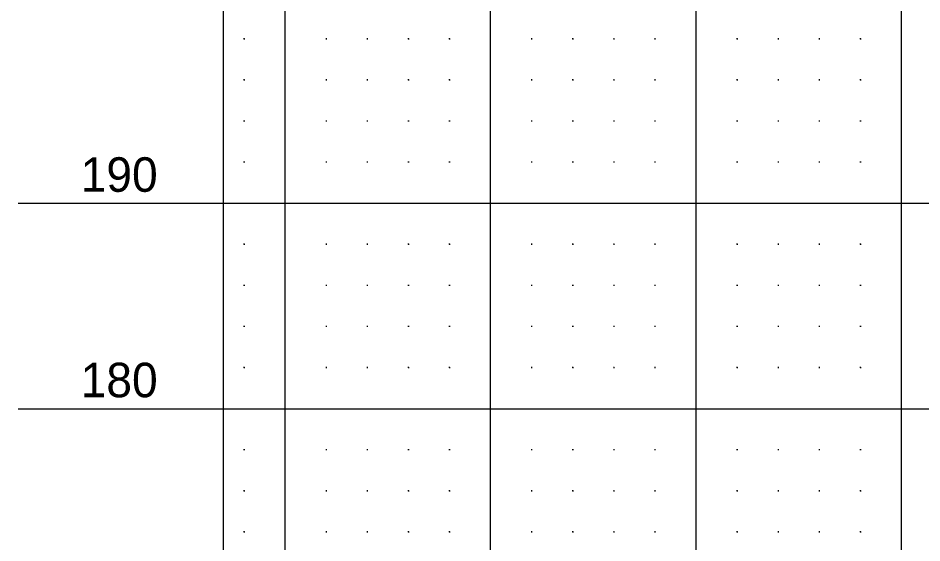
# Model space of a CAD drawing. Extents: x 471 to 2121, y 140 to 650.
# Drawn here: x 471.1 to 691, y 267.3 to 395.1 of the extents above; entities that cross this region are included whole.
import ezdxf

# ---------------------------------------------------------------- set-up
doc = ezdxf.new("R2010")
doc.units = 0
doc.layers.add('DSN_DRFT_Border Grid', color=7, linetype='Continuous')
doc.layers.add('DSN_RDWY_Prof Annotation', color=7, linetype='Continuous')

msp = doc.modelspace()

# ---------------------------------------------------------------- linework, layer by layer
at = {"layer": 'DSN_DRFT_Border Grid'}
for p, q in [((521.06, 150), (521.06, 650)), ((521.06, 150), (521.06, 650)), ((536.06, 150), (536.06, 650)), ((536.06, 150), (536.06, 650)), ((586.06, 150), (586.06, 650)), ((586.06, 150), (586.06, 650)), ((636.06, 150), (636.06, 650)), ((636.06, 150), (636.06, 650)), ((686.06, 150), (686.06, 650)), ((686.06, 150), (686.06, 650)), ((526.18, 390), (525.94, 390)), ((526.18, 390), (525.94, 390)), ((526.06, 390.12), (526.06, 389.88)), ((526.06, 390.12), (526.06, 389.88)), ((546.18, 390), (545.94, 390)), ((546.18, 390), (545.94, 390)), ((546.06, 390.12), (546.06, 389.88)), ((546.06, 390.12), (546.06, 389.88)), ((556.18, 390), (555.94, 390)), ((556.18, 390), (555.94, 390)), ((556.06, 390.12), (556.06, 389.88)), ((556.06, 390.12), (556.06, 389.88)), ((566.18, 390), (565.94, 390)), ((566.18, 390), (565.94, 390)), ((566.06, 390.12), (566.06, 389.88)), ((566.06, 390.12), (566.06, 389.88)), ((576.18, 390), (575.94, 390)), ((576.18, 390), (575.94, 390)), ((576.06, 390.12), (576.06, 389.88)), ((576.06, 390.12), (576.06, 389.88)), ((596.18, 390), (595.94, 390)), ((596.18, 390), (595.94, 390)), ((596.06, 390.12), (596.06, 389.88)), ((596.06, 390.12), (596.06, 389.88)), ((606.18, 390), (605.94, 390)), ((606.18, 390), (605.94, 390)), ((606.06, 390.12), (606.06, 389.88)), ((606.06, 390.12), (606.06, 389.88)), ((616.18, 390), (615.94, 390)), ((616.18, 390), (615.94, 390)), ((616.06, 390.12), (616.06, 389.88)), ((616.06, 390.12), (616.06, 389.88)), ((626.18, 390), (625.94, 390)), ((626.18, 390), (625.94, 390)), ((626.06, 390.12), (626.06, 389.88)), ((626.06, 390.12), (626.06, 389.88)), ((646.18, 390), (645.94, 390)), ((646.18, 390), (645.94, 390)), ((646.06, 390.12), (646.06, 389.88)), ((646.06, 390.12), (646.06, 389.88)), ((656.18, 390), (655.94, 390)), ((656.18, 390), (655.94, 390)), ((656.06, 390.12), (656.06, 389.88)), ((656.06, 390.12), (656.06, 389.88)), ((666.18, 390), (665.94, 390)), ((666.18, 390), (665.94, 390)), ((666.06, 390.12), (666.06, 389.88)), ((666.06, 390.12), (666.06, 389.88)), ((676.18, 390), (675.94, 390)), ((676.18, 390), (675.94, 390)), ((676.06, 390.12), (676.06, 389.88)), ((676.06, 390.12), (676.06, 389.88)), ((526.18, 380), (525.94, 380)), ((526.18, 380), (525.94, 380)), ((526.06, 380.12), (526.06, 379.88)), ((526.06, 380.12), (526.06, 379.88)), ((546.18, 380), (545.94, 380)), ((546.18, 380), (545.94, 380)), ((546.06, 380.12), (546.06, 379.88)), ((546.06, 380.12), (546.06, 379.88)), ((556.18, 380), (555.94, 380)), ((556.18, 380), (555.94, 380)), ((556.06, 380.12), (556.06, 379.88)), ((556.06, 380.12), (556.06, 379.88)), ((566.18, 380), (565.94, 380)), ((566.18, 380), (565.94, 380)), ((566.06, 380.12), (566.06, 379.88)), ((566.06, 380.12), (566.06, 379.88)), ((576.18, 380), (575.94, 380)), ((576.18, 380), (575.94, 380)), ((576.06, 380.12), (576.06, 379.88)), ((576.06, 380.12), (576.06, 379.88)), ((596.18, 380), (595.94, 380)), ((596.18, 380), (595.94, 380)), ((596.06, 380.12), (596.06, 379.88)), ((596.06, 380.12), (596.06, 379.88)), ((606.18, 380), (605.94, 380)), ((606.18, 380), (605.94, 380)), ((606.06, 380.12), (606.06, 379.88)), ((606.06, 380.12), (606.06, 379.88)), ((616.18, 380), (615.94, 380)), ((616.18, 380), (615.94, 380)), ((616.06, 380.12), (616.06, 379.88)), ((616.06, 380.12), (616.06, 379.88)), ((626.18, 380), (625.94, 380)), ((626.18, 380), (625.94, 380)), ((626.06, 380.12), (626.06, 379.88)), ((626.06, 380.12), (626.06, 379.88)), ((646.18, 380), (645.94, 380)), ((646.18, 380), (645.94, 380)), ((646.06, 380.12), (646.06, 379.88)), ((646.06, 380.12), (646.06, 379.88)), ((656.18, 380), (655.94, 380)), ((656.18, 380), (655.94, 380)), ((656.06, 380.12), (656.06, 379.88)), ((656.06, 380.12), (656.06, 379.88)), ((666.18, 380), (665.94, 380)), ((666.18, 380), (665.94, 380)), ((666.06, 380.12), (666.06, 379.88)), ((666.06, 380.12), (666.06, 379.88)), ((676.18, 380), (675.94, 380)), ((676.18, 380), (675.94, 380)), ((676.06, 380.12), (676.06, 379.88)), ((676.06, 380.12), (676.06, 379.88)), ((526.18, 370), (525.94, 370)), ((526.18, 370), (525.94, 370)), ((526.06, 370.12), (526.06, 369.88)), ((526.06, 370.12), (526.06, 369.88)), ((546.18, 370), (545.94, 370)), ((546.18, 370), (545.94, 370)), ((546.06, 370.12), (546.06, 369.88)), ((546.06, 370.12), (546.06, 369.88)), ((556.18, 370), (555.94, 370)), ((556.18, 370), (555.94, 370)), ((556.06, 370.12), (556.06, 369.88)), ((556.06, 370.12), (556.06, 369.88)), ((566.18, 370), (565.94, 370)), ((566.18, 370), (565.94, 370)), ((566.06, 370.12), (566.06, 369.88)), ((566.06, 370.12), (566.06, 369.88)), ((576.18, 370), (575.94, 370)), ((576.18, 370), (575.94, 370)), ((576.06, 370.12), (576.06, 369.88)), ((576.06, 370.12), (576.06, 369.88)), ((596.18, 370), (595.94, 370)), ((596.18, 370), (595.94, 370)), ((596.06, 370.12), (596.06, 369.88)), ((596.06, 370.12), (596.06, 369.88)), ((606.18, 370), (605.94, 370)), ((606.18, 370), (605.94, 370)), ((606.06, 370.12), (606.06, 369.88)), ((606.06, 370.12), (606.06, 369.88)), ((616.18, 370), (615.94, 370)), ((616.18, 370), (615.94, 370)), ((616.06, 370.12), (616.06, 369.88)), ((616.06, 370.12), (616.06, 369.88)), ((626.18, 370), (625.94, 370)), ((626.18, 370), (625.94, 370)), ((626.06, 370.12), (626.06, 369.88)), ((626.06, 370.12), (626.06, 369.88)), ((646.18, 370), (645.94, 370)), ((646.18, 370), (645.94, 370)), ((646.06, 370.12), (646.06, 369.88)), ((646.06, 370.12), (646.06, 369.88)), ((656.18, 370), (655.94, 370)), ((656.18, 370), (655.94, 370)), ((656.06, 370.12), (656.06, 369.88)), ((656.06, 370.12), (656.06, 369.88)), ((666.18, 370), (665.94, 370)), ((666.18, 370), (665.94, 370)), ((666.06, 370.12), (666.06, 369.88)), ((666.06, 370.12), (666.06, 369.88)), ((676.18, 370), (675.94, 370)), ((676.18, 370), (675.94, 370)), ((676.06, 370.12), (676.06, 369.88)), ((676.06, 370.12), (676.06, 369.88)), ((526.18, 360), (525.94, 360)), ((526.18, 360), (525.94, 360)), ((526.06, 360.12), (526.06, 359.88)), ((526.06, 360.12), (526.06, 359.88)), ((546.18, 360), (545.94, 360)), ((546.18, 360), (545.94, 360)), ((546.06, 360.12), (546.06, 359.88)), ((546.06, 360.12), (546.06, 359.88)), ((556.18, 360), (555.94, 360)), ((556.18, 360), (555.94, 360)), ((556.06, 360.12), (556.06, 359.88)), ((556.06, 360.12), (556.06, 359.88)), ((566.18, 360), (565.94, 360)), ((566.18, 360), (565.94, 360)), ((566.06, 360.12), (566.06, 359.88)), ((566.06, 360.12), (566.06, 359.88)), ((576.18, 360), (575.94, 360)), ((576.18, 360), (575.94, 360)), ((576.06, 360.12), (576.06, 359.88)), ((576.06, 360.12), (576.06, 359.88)), ((596.18, 360), (595.94, 360)), ((596.18, 360), (595.94, 360)), ((596.06, 360.12), (596.06, 359.88)), ((596.06, 360.12), (596.06, 359.88)), ((606.18, 360), (605.94, 360)), ((606.18, 360), (605.94, 360)), ((606.06, 360.12), (606.06, 359.88)), ((606.06, 360.12), (606.06, 359.88)), ((616.18, 360), (615.94, 360)), ((616.18, 360), (615.94, 360)), ((616.06, 360.12), (616.06, 359.88)), ((616.06, 360.12), (616.06, 359.88)), ((626.18, 360), (625.94, 360)), ((626.18, 360), (625.94, 360)), ((626.06, 360.12), (626.06, 359.88)), ((626.06, 360.12), (626.06, 359.88)), ((646.18, 360), (645.94, 360)), ((646.18, 360), (645.94, 360)), ((646.06, 360.12), (646.06, 359.88)), ((646.06, 360.12), (646.06, 359.88)), ((656.18, 360), (655.94, 360)), ((656.18, 360), (655.94, 360)), ((656.06, 360.12), (656.06, 359.88)), ((656.06, 360.12), (656.06, 359.88)), ((666.18, 360), (665.94, 360)), ((666.18, 360), (665.94, 360)), ((666.06, 360.12), (666.06, 359.88)), ((666.06, 360.12), (666.06, 359.88)), ((676.18, 360), (675.94, 360)), ((676.18, 360), (675.94, 360)), ((676.06, 360.12), (676.06, 359.88)), ((676.06, 360.12), (676.06, 359.88)), ((471.06, 350), (521.06, 350)), ((521.06, 350), (2071.06, 350)), ((521.06, 350), (2071.06, 350)), ((526.18, 340), (525.94, 340)), ((526.18, 340), (525.94, 340)), ((526.06, 340.12), (526.06, 339.88)), ((526.06, 340.12), (526.06, 339.88)), ((546.18, 340), (545.94, 340)), ((546.18, 340), (545.94, 340)), ((546.06, 340.12), (546.06, 339.88)), ((546.06, 340.12), (546.06, 339.88)), ((556.18, 340), (555.94, 340)), ((556.18, 340), (555.94, 340)), ((556.06, 340.12), (556.06, 339.88)), ((556.06, 340.12), (556.06, 339.88)), ((566.18, 340), (565.94, 340)), ((566.18, 340), (565.94, 340)), ((566.06, 340.12), (566.06, 339.88)), ((566.06, 340.12), (566.06, 339.88)), ((576.18, 340), (575.94, 340)), ((576.18, 340), (575.94, 340)), ((576.06, 340.12), (576.06, 339.88)), ((576.06, 340.12), (576.06, 339.88)), ((596.18, 340), (595.94, 340)), ((596.18, 340), (595.94, 340)), ((596.06, 340.12), (596.06, 339.88)), ((596.06, 340.12), (596.06, 339.88)), ((606.18, 340), (605.94, 340)), ((606.18, 340), (605.94, 340)), ((606.06, 340.12), (606.06, 339.88)), ((606.06, 340.12), (606.06, 339.88)), ((616.18, 340), (615.94, 340)), ((616.18, 340), (615.94, 340)), ((616.06, 340.12), (616.06, 339.88)), ((616.06, 340.12), (616.06, 339.88)), ((626.18, 340), (625.94, 340)), ((626.18, 340), (625.94, 340)), ((626.06, 340.12), (626.06, 339.88)), ((626.06, 340.12), (626.06, 339.88)), ((646.18, 340), (645.94, 340)), ((646.18, 340), (645.94, 340)), ((646.06, 340.12), (646.06, 339.88)), ((646.06, 340.12), (646.06, 339.88)), ((656.18, 340), (655.94, 340)), ((656.18, 340), (655.94, 340)), ((656.06, 340.12), (656.06, 339.88)), ((656.06, 340.12), (656.06, 339.88)), ((666.18, 340), (665.94, 340)), ((666.18, 340), (665.94, 340)), ((666.06, 340.12), (666.06, 339.88)), ((666.06, 340.12), (666.06, 339.88)), ((676.18, 340), (675.94, 340)), ((676.18, 340), (675.94, 340)), ((676.06, 340.12), (676.06, 339.88)), ((676.06, 340.12), (676.06, 339.88)), ((526.18, 330), (525.94, 330)), ((526.18, 330), (525.94, 330)), ((526.06, 330.12), (526.06, 329.88)), ((526.06, 330.12), (526.06, 329.88)), ((546.18, 330), (545.94, 330)), ((546.18, 330), (545.94, 330)), ((546.06, 330.12), (546.06, 329.88)), ((546.06, 330.12), (546.06, 329.88)), ((556.18, 330), (555.94, 330)), ((556.18, 330), (555.94, 330)), ((556.06, 330.12), (556.06, 329.88)), ((556.06, 330.12), (556.06, 329.88)), ((566.18, 330), (565.94, 330)), ((566.18, 330), (565.94, 330)), ((566.06, 330.12), (566.06, 329.88)), ((566.06, 330.12), (566.06, 329.88)), ((576.18, 330), (575.94, 330)), ((576.18, 330), (575.94, 330)), ((576.06, 330.12), (576.06, 329.88)), ((576.06, 330.12), (576.06, 329.88)), ((596.18, 330), (595.94, 330)), ((596.18, 330), (595.94, 330)), ((596.06, 330.12), (596.06, 329.88)), ((596.06, 330.12), (596.06, 329.88)), ((606.18, 330), (605.94, 330)), ((606.18, 330), (605.94, 330)), ((606.06, 330.12), (606.06, 329.88)), ((606.06, 330.12), (606.06, 329.88)), ((616.18, 330), (615.94, 330)), ((616.18, 330), (615.94, 330)), ((616.06, 330.12), (616.06, 329.88)), ((616.06, 330.12), (616.06, 329.88)), ((626.18, 330), (625.94, 330)), ((626.18, 330), (625.94, 330)), ((626.06, 330.12), (626.06, 329.88)), ((626.06, 330.12), (626.06, 329.88)), ((646.18, 330), (645.94, 330)), ((646.18, 330), (645.94, 330)), ((646.06, 330.12), (646.06, 329.88)), ((646.06, 330.12), (646.06, 329.88)), ((656.18, 330), (655.94, 330)), ((656.18, 330), (655.94, 330)), ((656.06, 330.12), (656.06, 329.88)), ((656.06, 330.12), (656.06, 329.88)), ((666.18, 330), (665.94, 330)), ((666.18, 330), (665.94, 330)), ((666.06, 330.12), (666.06, 329.88)), ((666.06, 330.12), (666.06, 329.88)), ((676.18, 330), (675.94, 330)), ((676.18, 330), (675.94, 330)), ((676.06, 330.12), (676.06, 329.88)), ((676.06, 330.12), (676.06, 329.88)), ((526.18, 320), (525.94, 320)), ((526.18, 320), (525.94, 320)), ((526.06, 320.12), (526.06, 319.88)), ((526.06, 320.12), (526.06, 319.88)), ((546.18, 320), (545.94, 320)), ((546.18, 320), (545.94, 320)), ((546.06, 320.12), (546.06, 319.88)), ((546.06, 320.12), (546.06, 319.88)), ((556.18, 320), (555.94, 320)), ((556.18, 320), (555.94, 320)), ((556.06, 320.12), (556.06, 319.88)), ((556.06, 320.12), (556.06, 319.88)), ((566.18, 320), (565.94, 320)), ((566.18, 320), (565.94, 320)), ((566.06, 320.12), (566.06, 319.88)), ((566.06, 320.12), (566.06, 319.88)), ((576.18, 320), (575.94, 320)), ((576.18, 320), (575.94, 320)), ((576.06, 320.12), (576.06, 319.88)), ((576.06, 320.12), (576.06, 319.88)), ((596.18, 320), (595.94, 320)), ((596.18, 320), (595.94, 320)), ((596.06, 320.12), (596.06, 319.88)), ((596.06, 320.12), (596.06, 319.88)), ((606.18, 320), (605.94, 320)), ((606.18, 320), (605.94, 320)), ((606.06, 320.12), (606.06, 319.88)), ((606.06, 320.12), (606.06, 319.88)), ((616.18, 320), (615.94, 320)), ((616.18, 320), (615.94, 320)), ((616.06, 320.12), (616.06, 319.88)), ((616.06, 320.12), (616.06, 319.88)), ((626.18, 320), (625.94, 320)), ((626.18, 320), (625.94, 320)), ((626.06, 320.12), (626.06, 319.88)), ((626.06, 320.12), (626.06, 319.88)), ((646.18, 320), (645.94, 320)), ((646.18, 320), (645.94, 320)), ((646.06, 320.12), (646.06, 319.88)), ((646.06, 320.12), (646.06, 319.88)), ((656.18, 320), (655.94, 320)), ((656.18, 320), (655.94, 320)), ((656.06, 320.12), (656.06, 319.88)), ((656.06, 320.12), (656.06, 319.88)), ((666.18, 320), (665.94, 320)), ((666.18, 320), (665.94, 320)), ((666.06, 320.12), (666.06, 319.88)), ((666.06, 320.12), (666.06, 319.88)), ((676.18, 320), (675.94, 320)), ((676.18, 320), (675.94, 320)), ((676.06, 320.12), (676.06, 319.88)), ((676.06, 320.12), (676.06, 319.88)), ((526.18, 310), (525.94, 310)), ((526.18, 310), (525.94, 310)), ((526.06, 310.12), (526.06, 309.88)), ((526.06, 310.12), (526.06, 309.88)), ((546.18, 310), (545.94, 310)), ((546.18, 310), (545.94, 310)), ((546.06, 310.12), (546.06, 309.88)), ((546.06, 310.12), (546.06, 309.88)), ((556.18, 310), (555.94, 310)), ((556.18, 310), (555.94, 310)), ((556.06, 310.12), (556.06, 309.88)), ((556.06, 310.12), (556.06, 309.88)), ((566.18, 310), (565.94, 310)), ((566.18, 310), (565.94, 310)), ((566.06, 310.12), (566.06, 309.88)), ((566.06, 310.12), (566.06, 309.88)), ((576.18, 310), (575.94, 310)), ((576.18, 310), (575.94, 310)), ((576.06, 310.12), (576.06, 309.88)), ((576.06, 310.12), (576.06, 309.88)), ((596.18, 310), (595.94, 310)), ((596.18, 310), (595.94, 310)), ((596.06, 310.12), (596.06, 309.88)), ((596.06, 310.12), (596.06, 309.88)), ((606.18, 310), (605.94, 310)), ((606.18, 310), (605.94, 310)), ((606.06, 310.12), (606.06, 309.88)), ((606.06, 310.12), (606.06, 309.88)), ((616.18, 310), (615.94, 310)), ((616.18, 310), (615.94, 310)), ((616.06, 310.12), (616.06, 309.88)), ((616.06, 310.12), (616.06, 309.88)), ((626.18, 310), (625.94, 310)), ((626.18, 310), (625.94, 310)), ((626.06, 310.12), (626.06, 309.88)), ((626.06, 310.12), (626.06, 309.88)), ((646.18, 310), (645.94, 310)), ((646.18, 310), (645.94, 310)), ((646.06, 310.12), (646.06, 309.88)), ((646.06, 310.12), (646.06, 309.88)), ((656.18, 310), (655.94, 310)), ((656.18, 310), (655.94, 310)), ((656.06, 310.12), (656.06, 309.88)), ((656.06, 310.12), (656.06, 309.88)), ((666.18, 310), (665.94, 310)), ((666.18, 310), (665.94, 310)), ((666.06, 310.12), (666.06, 309.88)), ((666.06, 310.12), (666.06, 309.88)), ((676.18, 310), (675.94, 310)), ((676.18, 310), (675.94, 310)), ((676.06, 310.12), (676.06, 309.88)), ((676.06, 310.12), (676.06, 309.88)), ((471.06, 300), (521.06, 300)), ((521.06, 300), (2071.06, 300)), ((521.06, 300), (2071.06, 300)), ((526.18, 290), (525.94, 290)), ((526.18, 290), (525.94, 290)), ((526.06, 290.12), (526.06, 289.88)), ((526.06, 290.12), (526.06, 289.88)), ((546.18, 290), (545.94, 290)), ((546.18, 290), (545.94, 290)), ((546.06, 290.12), (546.06, 289.88)), ((546.06, 290.12), (546.06, 289.88)), ((556.18, 290), (555.94, 290)), ((556.18, 290), (555.94, 290)), ((556.06, 290.12), (556.06, 289.88)), ((556.06, 290.12), (556.06, 289.88)), ((566.18, 290), (565.94, 290)), ((566.18, 290), (565.94, 290)), ((566.06, 290.12), (566.06, 289.88)), ((566.06, 290.12), (566.06, 289.88)), ((576.18, 290), (575.94, 290)), ((576.18, 290), (575.94, 290)), ((576.06, 290.12), (576.06, 289.88)), ((576.06, 290.12), (576.06, 289.88)), ((596.18, 290), (595.94, 290)), ((596.18, 290), (595.94, 290)), ((596.06, 290.12), (596.06, 289.88)), ((596.06, 290.12), (596.06, 289.88)), ((606.18, 290), (605.94, 290)), ((606.18, 290), (605.94, 290)), ((606.06, 290.12), (606.06, 289.88)), ((606.06, 290.12), (606.06, 289.88)), ((616.18, 290), (615.94, 290)), ((616.18, 290), (615.94, 290)), ((616.06, 290.12), (616.06, 289.88)), ((616.06, 290.12), (616.06, 289.88)), ((626.18, 290), (625.94, 290)), ((626.18, 290), (625.94, 290)), ((626.06, 290.12), (626.06, 289.88)), ((626.06, 290.12), (626.06, 289.88)), ((646.18, 290), (645.94, 290)), ((646.18, 290), (645.94, 290)), ((646.06, 290.12), (646.06, 289.88)), ((646.06, 290.12), (646.06, 289.88)), ((656.18, 290), (655.94, 290)), ((656.18, 290), (655.94, 290)), ((656.06, 290.12), (656.06, 289.88)), ((656.06, 290.12), (656.06, 289.88)), ((666.18, 290), (665.94, 290)), ((666.18, 290), (665.94, 290)), ((666.06, 290.12), (666.06, 289.88)), ((666.06, 290.12), (666.06, 289.88)), ((676.18, 290), (675.94, 290)), ((676.18, 290), (675.94, 290)), ((676.06, 290.12), (676.06, 289.88)), ((676.06, 290.12), (676.06, 289.88)), ((526.18, 280), (525.94, 280)), ((526.18, 280), (525.94, 280)), ((526.06, 280.12), (526.06, 279.88)), ((526.06, 280.12), (526.06, 279.88)), ((546.18, 280), (545.94, 280)), ((546.18, 280), (545.94, 280)), ((546.06, 280.12), (546.06, 279.88)), ((546.06, 280.12), (546.06, 279.88)), ((556.18, 280), (555.94, 280)), ((556.18, 280), (555.94, 280)), ((556.06, 280.12), (556.06, 279.88)), ((556.06, 280.12), (556.06, 279.88)), ((566.18, 280), (565.94, 280)), ((566.18, 280), (565.94, 280)), ((566.06, 280.12), (566.06, 279.88)), ((566.06, 280.12), (566.06, 279.88)), ((576.18, 280), (575.94, 280)), ((576.18, 280), (575.94, 280)), ((576.06, 280.12), (576.06, 279.88)), ((576.06, 280.12), (576.06, 279.88)), ((596.18, 280), (595.94, 280)), ((596.18, 280), (595.94, 280)), ((596.06, 280.12), (596.06, 279.88)), ((596.06, 280.12), (596.06, 279.88)), ((606.18, 280), (605.94, 280)), ((606.18, 280), (605.94, 280)), ((606.06, 280.12), (606.06, 279.88)), ((606.06, 280.12), (606.06, 279.88)), ((616.18, 280), (615.94, 280)), ((616.18, 280), (615.94, 280)), ((616.06, 280.12), (616.06, 279.88)), ((616.06, 280.12), (616.06, 279.88)), ((626.18, 280), (625.94, 280)), ((626.18, 280), (625.94, 280)), ((626.06, 280.12), (626.06, 279.88)), ((626.06, 280.12), (626.06, 279.88)), ((646.18, 280), (645.94, 280)), ((646.18, 280), (645.94, 280)), ((646.06, 280.12), (646.06, 279.88)), ((646.06, 280.12), (646.06, 279.88)), ((656.18, 280), (655.94, 280)), ((656.18, 280), (655.94, 280)), ((656.06, 280.12), (656.06, 279.88)), ((656.06, 280.12), (656.06, 279.88)), ((666.18, 280), (665.94, 280)), ((666.18, 280), (665.94, 280)), ((666.06, 280.12), (666.06, 279.88)), ((666.06, 280.12), (666.06, 279.88)), ((676.18, 280), (675.94, 280)), ((676.18, 280), (675.94, 280)), ((676.06, 280.12), (676.06, 279.88)), ((676.06, 280.12), (676.06, 279.88)), ((526.18, 270), (525.94, 270)), ((526.18, 270), (525.94, 270)), ((526.06, 270.12), (526.06, 269.88)), ((526.06, 270.12), (526.06, 269.88)), ((546.18, 270), (545.94, 270)), ((546.18, 270), (545.94, 270)), ((546.06, 270.12), (546.06, 269.88)), ((546.06, 270.12), (546.06, 269.88)), ((556.18, 270), (555.94, 270)), ((556.18, 270), (555.94, 270)), ((556.06, 270.12), (556.06, 269.88)), ((556.06, 270.12), (556.06, 269.88)), ((566.18, 270), (565.94, 270)), ((566.18, 270), (565.94, 270)), ((566.06, 270.12), (566.06, 269.88)), ((566.06, 270.12), (566.06, 269.88)), ((576.18, 270), (575.94, 270)), ((576.18, 270), (575.94, 270)), ((576.06, 270.12), (576.06, 269.88)), ((576.06, 270.12), (576.06, 269.88)), ((596.18, 270), (595.94, 270)), ((596.18, 270), (595.94, 270)), ((596.06, 270.12), (596.06, 269.88)), ((596.06, 270.12), (596.06, 269.88)), ((606.18, 270), (605.94, 270)), ((606.18, 270), (605.94, 270)), ((606.06, 270.12), (606.06, 269.88)), ((606.06, 270.12), (606.06, 269.88)), ((616.18, 270), (615.94, 270)), ((616.18, 270), (615.94, 270)), ((616.06, 270.12), (616.06, 269.88)), ((616.06, 270.12), (616.06, 269.88)), ((626.18, 270), (625.94, 270)), ((626.18, 270), (625.94, 270)), ((626.06, 270.12), (626.06, 269.88)), ((626.06, 270.12), (626.06, 269.88)), ((646.18, 270), (645.94, 270)), ((646.18, 270), (645.94, 270)), ((646.06, 270.12), (646.06, 269.88)), ((646.06, 270.12), (646.06, 269.88)), ((656.18, 270), (655.94, 270)), ((656.18, 270), (655.94, 270)), ((656.06, 270.12), (656.06, 269.88)), ((656.06, 270.12), (656.06, 269.88)), ((666.18, 270), (665.94, 270)), ((666.18, 270), (665.94, 270)), ((666.06, 270.12), (666.06, 269.88)), ((666.06, 270.12), (666.06, 269.88)), ((676.18, 270), (675.94, 270)), ((676.18, 270), (675.94, 270)), ((676.06, 270.12), (676.06, 269.88)), ((676.06, 270.12), (676.06, 269.88))]:
    msp.add_line(p, q, dxfattribs=at)

# ---------------------------------------------------------------- texts
at = {"layer": 'DSN_RDWY_Prof Annotation'}
for s, p in [('190', (486.3, 352.78)), ('190', (486.3, 352.78)), ('180', (486.3, 302.78)), ('180', (486.3, 302.78))]:
    msp.add_text(s, height=8.4, dxfattribs=at).set_placement(p)

doc.saveas('drawing.dxf')
